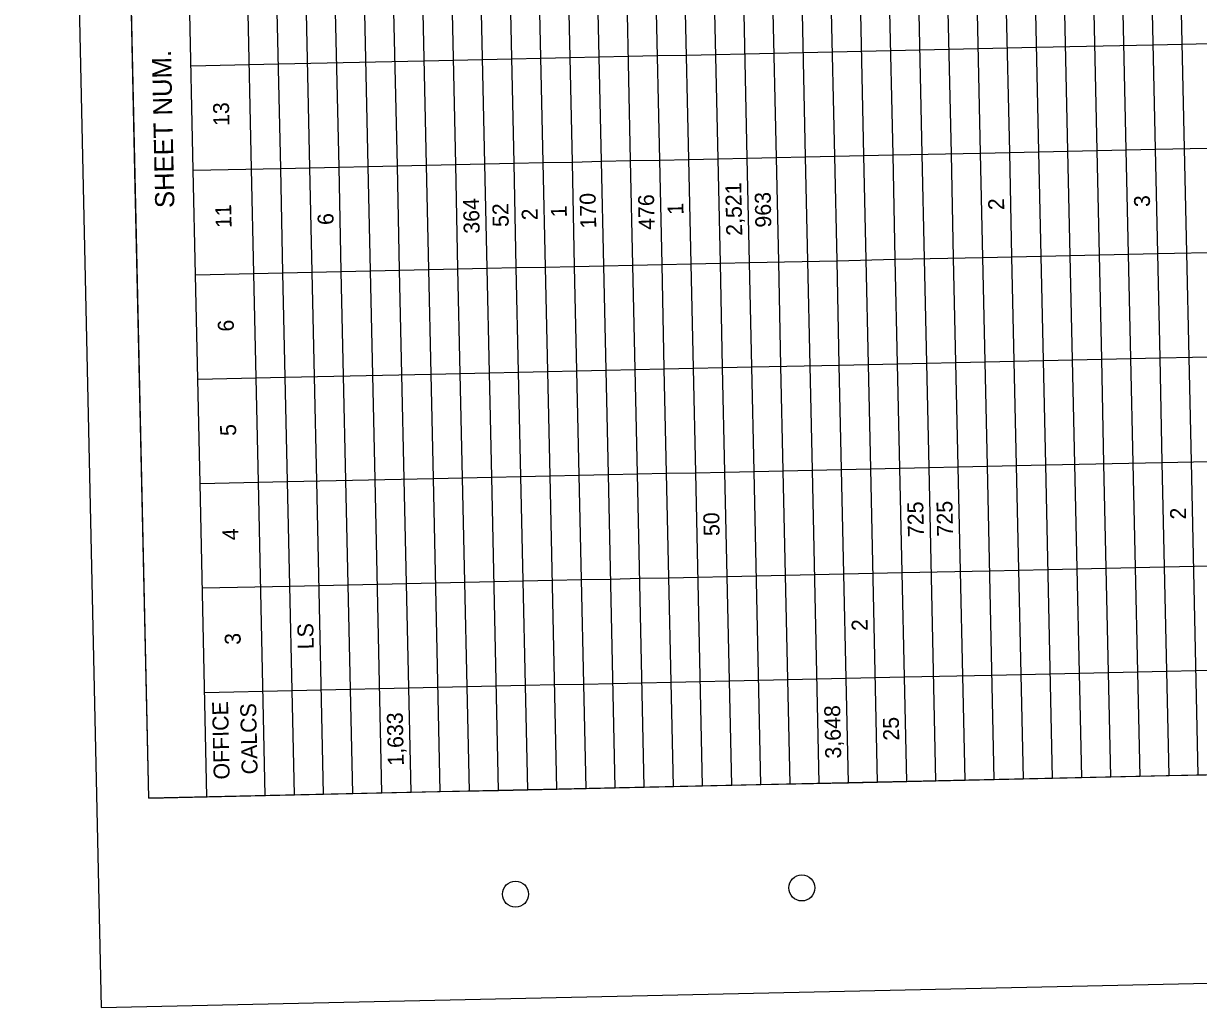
# Model space of a CAD drawing. Extents: x -14 to 2448635, y -29 to 504795.
# Drawn here: x 2448612.38 to 2448623.66, y 504719.75 to 504729.2 of the extents above; entities that cross this region are included whole.
import ezdxf

# ---------------------------------------------------------------- set-up
doc = ezdxf.new("R2010")
doc.units = 0
for name, color, linetype in [('SH_Border', 7, 'Continuous'), ('SH_Cut_Line', 7, 'Continuous'), ('SH_Data', 7, 'Continuous'), ('TX_P_1', 7, 'Continuous')]:
    doc.layers.add(name, color=color, linetype=linetype)

msp = doc.modelspace()

# ---------------------------------------------------------------- linework, layer by layer
at = {"layer": 'SH_Border'}
msp.add_lwpolyline([(2448613.583, 504721.765), (2448612.892, 504753.257), (2448633.887, 504753.718), (2448634.578, 504722.225)], close=True, dxfattribs=at)
for centre in [(2448619.853, 504720.902), (2448617.104, 504720.842)]:
    msp.add_circle(centre, 0.125, dxfattribs=at)
at = {"layer": 'SH_Cut_Line'}
msp.add_lwpolyline([(2448635.121, 504720.237), (2448634.376, 504754.228), (2448612.381, 504753.746), (2448613.127, 504719.754)], close=True, dxfattribs=at)
at = {"layer": 'SH_Data'}
for p, q in [((2448620.449, 504727.932), (2448620.317, 504733.946)), ((2448620.729, 504727.938), (2448620.597, 504733.952)), ((2448621.009, 504727.944), (2448620.877, 504733.958)), ((2448621.289, 504727.95), (2448621.157, 504733.964)), ((2448621.569, 504727.956), (2448621.437, 504733.97)), ((2448621.849, 504727.963), (2448621.717, 504733.976)), ((2448622.129, 504727.969), (2448621.997, 504733.982)), ((2448622.408, 504727.975), (2448622.277, 504733.989)), ((2448622.688, 504727.981), (2448622.556, 504733.995)), ((2448622.968, 504727.987), (2448622.836, 504734.001)), ((2448623.248, 504727.993), (2448623.116, 504734.007)), ((2448623.528, 504727.999), (2448623.396, 504734.013)), ((2448615.13, 504727.815), (2448614.998, 504733.829)), ((2448615.41, 504727.821), (2448615.278, 504733.835)), ((2448615.69, 504727.827), (2448615.558, 504733.841)), ((2448615.97, 504727.834), (2448615.838, 504733.847)), ((2448616.25, 504727.84), (2448616.118, 504733.853)), ((2448616.53, 504727.846), (2448616.398, 504733.86)), ((2448616.81, 504727.852), (2448616.678, 504733.866)), ((2448617.09, 504727.858), (2448616.958, 504733.872)), ((2448617.37, 504727.864), (2448617.238, 504733.878)), ((2448617.65, 504727.87), (2448617.518, 504733.884)), ((2448617.93, 504727.877), (2448617.798, 504733.89)), ((2448618.209, 504727.883), (2448618.078, 504733.896)), ((2448618.489, 504727.889), (2448618.357, 504733.903)), ((2448618.769, 504727.895), (2448618.637, 504733.909)), ((2448619.049, 504727.901), (2448618.917, 504733.915)), ((2448619.329, 504727.907), (2448619.197, 504733.921)), ((2448619.609, 504727.913), (2448619.477, 504733.927)), ((2448619.889, 504727.92), (2448619.757, 504733.933)), ((2448620.169, 504727.926), (2448620.037, 504733.939)), ((2448613.451, 504727.778), (2448613.319, 504733.792)), ((2448614.01, 504727.791), (2448613.879, 504733.804)), ((2448614.57, 504727.803), (2448614.438, 504733.817)), ((2448614.85, 504727.809), (2448614.718, 504733.823)), ((2448622.107, 504728.971), (2448623.226, 504728.996)), ((2448623.226, 504728.996), (2448624.626, 504729.026)), ((2448617.068, 504728.86), (2448617.348, 504728.867)), ((2448617.348, 504728.867), (2448617.628, 504728.873)), ((2448617.628, 504728.873), (2448617.908, 504728.879)), ((2448617.908, 504728.879), (2448618.187, 504728.885)), ((2448618.187, 504728.885), (2448618.467, 504728.891)), ((2448618.467, 504728.891), (2448618.747, 504728.897)), ((2448618.747, 504728.897), (2448619.027, 504728.903)), ((2448619.027, 504728.903), (2448619.307, 504728.91)), ((2448619.307, 504728.91), (2448620.147, 504728.928)), ((2448620.147, 504728.928), (2448620.707, 504728.94)), ((2448620.707, 504728.94), (2448621.547, 504728.959)), ((2448621.547, 504728.959), (2448622.107, 504728.971)), ((2448613.989, 504728.793), (2448614.828, 504728.811)), ((2448614.828, 504728.811), (2448616.228, 504728.842)), ((2448616.228, 504728.842), (2448616.788, 504728.854)), ((2448616.788, 504728.854), (2448617.068, 504728.86)), ((2448621.569, 504727.956), (2448622.129, 504727.969)), ((2448621.871, 504726.96), (2448621.849, 504727.963)), ((2448622.129, 504727.969), (2448623.248, 504727.993)), ((2448622.151, 504726.966), (2448622.129, 504727.969)), ((2448622.43, 504726.973), (2448622.408, 504727.975)), ((2448622.71, 504726.979), (2448622.688, 504727.981)), ((2448622.99, 504726.985), (2448622.968, 504727.987)), ((2448623.248, 504727.993), (2448624.648, 504728.024)), ((2448623.27, 504726.991), (2448623.248, 504727.993)), ((2448623.55, 504726.997), (2448623.528, 504727.999)), ((2448616.25, 504727.84), (2448616.81, 504727.852)), ((2448616.81, 504727.852), (2448617.09, 504727.858)), ((2448616.832, 504726.85), (2448616.81, 504727.852)), ((2448617.09, 504727.858), (2448617.37, 504727.864)), ((2448617.112, 504726.856), (2448617.09, 504727.858)), ((2448617.37, 504727.864), (2448617.65, 504727.87)), ((2448617.392, 504726.862), (2448617.37, 504727.864)), ((2448617.65, 504727.87), (2448617.93, 504727.877)), ((2448617.672, 504726.868), (2448617.65, 504727.87)), ((2448617.93, 504727.877), (2448618.209, 504727.883)), ((2448617.952, 504726.874), (2448617.93, 504727.877)), ((2448618.209, 504727.883), (2448618.489, 504727.889)), ((2448618.231, 504726.88), (2448618.209, 504727.883)), ((2448618.489, 504727.889), (2448618.769, 504727.895)), ((2448618.511, 504726.887), (2448618.489, 504727.889)), ((2448618.769, 504727.895), (2448619.049, 504727.901)), ((2448618.791, 504726.893), (2448618.769, 504727.895)), ((2448619.049, 504727.901), (2448619.329, 504727.907)), ((2448619.071, 504726.899), (2448619.049, 504727.901)), ((2448619.329, 504727.907), (2448620.169, 504727.926)), ((2448619.351, 504726.905), (2448619.329, 504727.907)), ((2448619.631, 504726.911), (2448619.609, 504727.913)), ((2448619.911, 504726.917), (2448619.889, 504727.92)), ((2448620.169, 504727.926), (2448620.729, 504727.938)), ((2448620.191, 504726.923), (2448620.169, 504727.926)), ((2448620.471, 504726.93), (2448620.449, 504727.932)), ((2448620.729, 504727.938), (2448621.569, 504727.956)), ((2448620.751, 504726.936), (2448620.729, 504727.938)), ((2448621.031, 504726.942), (2448621.009, 504727.944)), ((2448621.311, 504726.948), (2448621.289, 504727.95)), ((2448621.591, 504726.954), (2448621.569, 504727.956)), ((2448613.473, 504726.776), (2448613.451, 504727.778)), ((2448614.01, 504727.791), (2448614.85, 504727.809)), ((2448614.032, 504726.788), (2448614.01, 504727.791)), ((2448614.592, 504726.801), (2448614.57, 504727.803)), ((2448614.85, 504727.809), (2448616.25, 504727.84)), ((2448614.872, 504726.807), (2448614.85, 504727.809)), ((2448615.152, 504726.813), (2448615.13, 504727.815)), ((2448615.432, 504726.819), (2448615.41, 504727.821)), ((2448615.712, 504726.825), (2448615.69, 504727.827)), ((2448615.992, 504726.831), (2448615.97, 504727.834)), ((2448616.272, 504726.837), (2448616.25, 504727.84)), ((2448616.552, 504726.844), (2448616.53, 504727.846)), ((2448620.751, 504726.936), (2448621.591, 504726.954)), ((2448621.333, 504725.946), (2448621.311, 504726.948)), ((2448621.591, 504726.954), (2448622.151, 504726.966)), ((2448621.613, 504725.952), (2448621.591, 504726.954)), ((2448621.893, 504725.958), (2448621.871, 504726.96)), ((2448622.151, 504726.966), (2448623.27, 504726.991)), ((2448622.173, 504725.964), (2448622.151, 504726.966)), ((2448622.452, 504725.97), (2448622.43, 504726.973)), ((2448622.732, 504725.976), (2448622.71, 504726.979)), ((2448623.012, 504725.983), (2448622.99, 504726.985)), ((2448623.27, 504726.991), (2448624.67, 504727.022)), ((2448623.292, 504725.989), (2448623.27, 504726.991)), ((2448623.572, 504725.995), (2448623.55, 504726.997)), ((2448614.872, 504726.807), (2448616.272, 504726.837)), ((2448616.272, 504726.837), (2448616.832, 504726.85)), ((2448616.294, 504725.835), (2448616.272, 504726.837)), ((2448616.574, 504725.841), (2448616.552, 504726.844)), ((2448616.832, 504726.85), (2448617.112, 504726.856)), ((2448616.854, 504725.847), (2448616.832, 504726.85)), ((2448617.112, 504726.856), (2448617.392, 504726.862)), ((2448617.134, 504725.854), (2448617.112, 504726.856)), ((2448617.392, 504726.862), (2448617.672, 504726.868)), ((2448617.414, 504725.86), (2448617.392, 504726.862)), ((2448617.672, 504726.868), (2448617.952, 504726.874)), ((2448617.694, 504725.866), (2448617.672, 504726.868)), ((2448617.952, 504726.874), (2448618.231, 504726.88)), ((2448617.974, 504725.872), (2448617.952, 504726.874)), ((2448618.231, 504726.88), (2448618.511, 504726.887)), ((2448618.253, 504725.878), (2448618.231, 504726.88)), ((2448618.511, 504726.887), (2448618.791, 504726.893)), ((2448618.533, 504725.884), (2448618.511, 504726.887)), ((2448618.791, 504726.893), (2448619.071, 504726.899)), ((2448618.813, 504725.89), (2448618.791, 504726.893)), ((2448619.071, 504726.899), (2448619.351, 504726.905)), ((2448619.093, 504725.897), (2448619.071, 504726.899)), ((2448619.351, 504726.905), (2448620.191, 504726.923)), ((2448619.373, 504725.903), (2448619.351, 504726.905)), ((2448619.653, 504725.909), (2448619.631, 504726.911)), ((2448619.933, 504725.915), (2448619.911, 504726.917)), ((2448620.191, 504726.923), (2448620.751, 504726.936)), ((2448620.213, 504725.921), (2448620.191, 504726.923)), ((2448620.493, 504725.927), (2448620.471, 504726.93)), ((2448620.773, 504725.933), (2448620.751, 504726.936)), ((2448621.053, 504725.94), (2448621.031, 504726.942)), ((2448613.495, 504725.774), (2448613.473, 504726.776)), ((2448614.032, 504726.788), (2448614.872, 504726.807)), ((2448614.054, 504725.786), (2448614.032, 504726.788)), ((2448614.614, 504725.798), (2448614.592, 504726.801)), ((2448614.894, 504725.804), (2448614.872, 504726.807)), ((2448615.174, 504725.811), (2448615.152, 504726.813)), ((2448615.454, 504725.817), (2448615.432, 504726.819)), ((2448615.734, 504725.823), (2448615.712, 504726.825)), ((2448616.014, 504725.829), (2448615.992, 504726.831)), ((2448620.213, 504725.921), (2448620.773, 504725.933)), ((2448620.773, 504725.933), (2448621.613, 504725.952)), ((2448620.795, 504724.931), (2448620.773, 504725.933)), ((2448621.075, 504724.937), (2448621.053, 504725.94)), ((2448621.355, 504724.943), (2448621.333, 504725.946)), ((2448621.613, 504725.952), (2448622.173, 504725.964)), ((2448621.635, 504724.95), (2448621.613, 504725.952)), ((2448621.915, 504724.956), (2448621.893, 504725.958)), ((2448622.173, 504725.964), (2448623.292, 504725.989)), ((2448622.195, 504724.962), (2448622.173, 504725.964)), ((2448622.474, 504724.968), (2448622.452, 504725.97)), ((2448622.754, 504724.974), (2448622.732, 504725.976)), ((2448623.034, 504724.98), (2448623.012, 504725.983)), ((2448623.292, 504725.989), (2448624.692, 504726.019)), ((2448623.314, 504724.986), (2448623.292, 504725.989)), ((2448623.594, 504724.993), (2448623.572, 504725.995)), ((2448614.894, 504725.804), (2448616.294, 504725.835)), ((2448615.756, 504724.821), (2448615.734, 504725.823)), ((2448616.036, 504724.827), (2448616.014, 504725.829)), ((2448616.294, 504725.835), (2448616.854, 504725.847)), ((2448616.316, 504724.833), (2448616.294, 504725.835)), ((2448616.596, 504724.839), (2448616.574, 504725.841)), ((2448616.854, 504725.847), (2448617.134, 504725.854)), ((2448616.876, 504724.845), (2448616.854, 504725.847)), ((2448617.134, 504725.854), (2448617.414, 504725.86)), ((2448617.156, 504724.851), (2448617.134, 504725.854)), ((2448617.414, 504725.86), (2448617.694, 504725.866)), ((2448617.436, 504724.857), (2448617.414, 504725.86)), ((2448617.694, 504725.866), (2448617.974, 504725.872)), ((2448617.716, 504724.864), (2448617.694, 504725.866)), ((2448617.974, 504725.872), (2448618.253, 504725.878)), ((2448617.996, 504724.87), (2448617.974, 504725.872)), ((2448618.253, 504725.878), (2448618.533, 504725.884)), ((2448618.275, 504724.876), (2448618.253, 504725.878)), ((2448618.533, 504725.884), (2448618.813, 504725.89)), ((2448618.555, 504724.882), (2448618.533, 504725.884)), ((2448618.813, 504725.89), (2448619.093, 504725.897)), ((2448618.835, 504724.888), (2448618.813, 504725.89)), ((2448619.093, 504725.897), (2448619.373, 504725.903)), ((2448619.115, 504724.894), (2448619.093, 504725.897)), ((2448619.373, 504725.903), (2448620.213, 504725.921)), ((2448619.395, 504724.9), (2448619.373, 504725.903)), ((2448619.675, 504724.907), (2448619.653, 504725.909)), ((2448619.955, 504724.913), (2448619.933, 504725.915)), ((2448620.235, 504724.919), (2448620.213, 504725.921)), ((2448620.515, 504724.925), (2448620.493, 504725.927)), ((2448613.517, 504724.771), (2448613.495, 504725.774)), ((2448614.054, 504725.786), (2448614.894, 504725.804)), ((2448614.076, 504724.784), (2448614.054, 504725.786)), ((2448614.636, 504724.796), (2448614.614, 504725.798)), ((2448614.916, 504724.802), (2448614.894, 504725.804)), ((2448615.196, 504724.808), (2448615.174, 504725.811)), ((2448615.476, 504724.814), (2448615.454, 504725.817)), ((2448619.395, 504724.9), (2448620.235, 504724.919)), ((2448620.235, 504724.919), (2448620.795, 504724.931)), ((2448620.301, 504721.912), (2448620.235, 504724.919)), ((2448620.581, 504721.918), (2448620.515, 504724.925)), ((2448620.795, 504724.931), (2448621.635, 504724.95)), ((2448620.861, 504721.924), (2448620.795, 504724.931)), ((2448621.141, 504721.93), (2448621.075, 504724.937)), ((2448621.421, 504721.937), (2448621.355, 504724.943)), ((2448621.635, 504724.95), (2448622.195, 504724.962)), ((2448621.701, 504721.943), (2448621.635, 504724.95)), ((2448621.981, 504721.949), (2448621.915, 504724.956)), ((2448622.195, 504724.962), (2448623.314, 504724.986)), ((2448622.26, 504721.955), (2448622.195, 504724.962)), ((2448622.54, 504721.961), (2448622.474, 504724.968)), ((2448622.82, 504721.967), (2448622.754, 504724.974)), ((2448623.1, 504721.973), (2448623.034, 504724.98)), ((2448623.314, 504724.986), (2448624.714, 504725.017)), ((2448623.38, 504721.98), (2448623.314, 504724.986)), ((2448623.66, 504721.986), (2448623.594, 504724.993)), ((2448614.916, 504724.802), (2448616.316, 504724.833)), ((2448615.262, 504721.801), (2448615.196, 504724.808)), ((2448615.542, 504721.808), (2448615.476, 504724.814)), ((2448615.822, 504721.814), (2448615.756, 504724.821)), ((2448616.102, 504721.82), (2448616.036, 504724.827)), ((2448616.316, 504724.833), (2448616.876, 504724.845)), ((2448616.382, 504721.826), (2448616.316, 504724.833)), ((2448616.662, 504721.832), (2448616.596, 504724.839)), ((2448616.876, 504724.845), (2448617.156, 504724.851)), ((2448616.942, 504721.838), (2448616.876, 504724.845)), ((2448617.156, 504724.851), (2448617.436, 504724.857)), ((2448617.222, 504721.844), (2448617.156, 504724.851)), ((2448617.436, 504724.857), (2448617.716, 504724.864)), ((2448617.502, 504721.851), (2448617.436, 504724.857)), ((2448617.716, 504724.864), (2448617.996, 504724.87)), ((2448617.782, 504721.857), (2448617.716, 504724.864)), ((2448617.996, 504724.87), (2448618.275, 504724.876)), ((2448618.061, 504721.863), (2448617.996, 504724.87)), ((2448618.275, 504724.876), (2448618.555, 504724.882)), ((2448618.341, 504721.869), (2448618.275, 504724.876)), ((2448618.555, 504724.882), (2448618.835, 504724.888)), ((2448618.621, 504721.875), (2448618.555, 504724.882)), ((2448618.835, 504724.888), (2448619.115, 504724.894)), ((2448618.901, 504721.881), (2448618.835, 504724.888)), ((2448619.115, 504724.894), (2448619.395, 504724.9)), ((2448619.181, 504721.887), (2448619.115, 504724.894)), ((2448619.461, 504721.894), (2448619.395, 504724.9)), ((2448619.741, 504721.9), (2448619.675, 504724.907)), ((2448620.021, 504721.906), (2448619.955, 504724.913)), ((2448613.583, 504721.765), (2448613.517, 504724.771)), ((2448614.076, 504724.784), (2448614.916, 504724.802)), ((2448614.142, 504721.777), (2448614.076, 504724.784)), ((2448614.702, 504721.789), (2448614.636, 504724.796)), ((2448614.982, 504721.795), (2448614.916, 504724.802)), ((2448623.336, 504723.984), (2448624.736, 504724.015)), ((2448619.417, 504723.898), (2448620.257, 504723.917)), ((2448620.257, 504723.917), (2448620.817, 504723.929)), ((2448620.817, 504723.929), (2448621.657, 504723.947)), ((2448621.657, 504723.947), (2448622.216, 504723.96)), ((2448622.216, 504723.96), (2448623.336, 504723.984)), ((2448614.098, 504723.781), (2448614.938, 504723.8)), ((2448614.938, 504723.8), (2448616.338, 504723.831)), ((2448616.338, 504723.831), (2448616.898, 504723.843)), ((2448616.898, 504723.843), (2448617.178, 504723.849)), ((2448617.178, 504723.849), (2448617.458, 504723.855)), ((2448617.458, 504723.855), (2448617.738, 504723.861)), ((2448617.738, 504723.861), (2448618.018, 504723.867)), ((2448618.018, 504723.867), (2448618.297, 504723.874)), ((2448618.297, 504723.874), (2448618.577, 504723.88)), ((2448618.577, 504723.88), (2448618.857, 504723.886)), ((2448618.857, 504723.886), (2448619.137, 504723.892)), ((2448619.137, 504723.892), (2448619.417, 504723.898)), ((2448623.358, 504722.982), (2448624.758, 504723.013)), ((2448618.879, 504722.884), (2448619.159, 504722.89)), ((2448619.159, 504722.89), (2448619.439, 504722.896)), ((2448619.439, 504722.896), (2448620.279, 504722.914)), ((2448620.279, 504722.914), (2448620.839, 504722.927)), ((2448620.839, 504722.927), (2448621.679, 504722.945)), ((2448621.679, 504722.945), (2448622.238, 504722.957)), ((2448622.238, 504722.957), (2448623.358, 504722.982)), ((2448614.12, 504722.779), (2448614.96, 504722.798)), ((2448614.96, 504722.798), (2448616.36, 504722.828)), ((2448616.36, 504722.828), (2448616.92, 504722.841)), ((2448616.92, 504722.841), (2448617.2, 504722.847)), ((2448617.2, 504722.847), (2448617.48, 504722.853)), ((2448617.48, 504722.853), (2448617.76, 504722.859)), ((2448617.76, 504722.859), (2448618.039, 504722.865)), ((2448618.039, 504722.865), (2448618.319, 504722.871)), ((2448618.319, 504722.871), (2448618.599, 504722.877)), ((2448618.599, 504722.877), (2448618.879, 504722.884)), ((2448623.38, 504721.98), (2448624.78, 504722.01)), ((2448618.341, 504721.869), (2448618.621, 504721.875)), ((2448618.621, 504721.875), (2448618.901, 504721.881)), ((2448618.901, 504721.881), (2448619.181, 504721.887)), ((2448619.181, 504721.887), (2448619.461, 504721.894)), ((2448619.461, 504721.894), (2448620.301, 504721.912)), ((2448620.301, 504721.912), (2448620.861, 504721.924)), ((2448620.861, 504721.924), (2448621.701, 504721.943)), ((2448621.701, 504721.943), (2448622.26, 504721.955)), ((2448622.26, 504721.955), (2448623.38, 504721.98)), ((2448613.583, 504721.765), (2448614.982, 504721.795)), ((2448614.982, 504721.795), (2448616.382, 504721.826)), ((2448616.382, 504721.826), (2448616.942, 504721.838)), ((2448616.942, 504721.838), (2448617.222, 504721.844)), ((2448617.222, 504721.844), (2448617.502, 504721.851)), ((2448617.502, 504721.851), (2448617.782, 504721.857)), ((2448617.782, 504721.857), (2448618.061, 504721.863)), ((2448618.061, 504721.863), (2448618.341, 504721.869))]:
    msp.add_line(p, q, dxfattribs=at)

# ---------------------------------------------------------------- texts
at = {"layer": 'TX_P_1'}
for s, height, p in [('SHEET NUM.', 0.184, (2448613.83, 504727.43)), ('13', 0.1533, (2448614.358, 504728.217)), ('2,521', 0.1533, (2448619.282, 504727.163)), ('364', 0.1533, (2448616.761, 504727.183)), ('170', 0.1533, (2448617.88, 504727.233)), ('476', 0.1533, (2448618.441, 504727.22)), ('963', 0.1533, (2448619.561, 504727.242)), ('2', 0.153, (2448621.797, 504727.41)), ('3', 0.153, (2448623.197, 504727.439)), ('11', 0.1533, (2448614.379, 504727.238)), ('52', 0.1533, (2448617.04, 504727.248)), ('2', 0.153, (2448617.318, 504727.312)), ('1', 0.153, (2448617.598, 504727.34)), ('1', 0.153, (2448618.718, 504727.365)), ('6', 0.153, (2448615.359, 504727.267)), ('6', 0.153, (2448614.401, 504726.244)), ('5', 0.153, (2448614.423, 504725.242)), ('725', 0.1533, (2448621.026, 504724.271)), ('725', 0.1533, (2448621.306, 504724.277)), ('50', 0.1533, (2448619.065, 504724.281)), ('2', 0.153, (2448623.543, 504724.44)), ('4', 0.153, (2448614.445, 504724.241)), ('2', 0.153, (2448620.486, 504723.37)), ('3', 0.153, (2448614.467, 504723.237)), ('LS', 0.1533, (2448615.168, 504723.194)), ('OFFICE', 0.1533, (2448614.361, 504721.944)), ('CALCS', 0.1533, (2448614.629, 504721.993)), ('1,633', 0.1533, (2448616.033, 504722.076)), ('3,648', 0.1533, (2448620.232, 504722.145)), ('25', 0.1533, (2448620.789, 504722.317))]:
    msp.add_text(s, height=height, rotation=91.2568, dxfattribs=at).set_placement(p)

doc.saveas('drawing.dxf')
